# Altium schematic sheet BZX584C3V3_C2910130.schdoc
size 127 x 101 mm
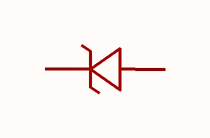
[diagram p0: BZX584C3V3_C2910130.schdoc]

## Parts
D?  bzx584c3v3_c2910130  [SOD-523_L1.2-W0.8-LS1.6-RD-2]  (value not drawn)

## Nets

Not connected (* = marked no-connect by the designer): D? 1(C) 2(A)

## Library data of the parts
D? = bzx584c3v3_c2910130: 二极管配置:1个独立式;稳压值(标称值):3.3V;稳压值(范围):3.1V~3.5V;耗散功率(Pd):150mW;; Manufacturer: CJ(江苏长电/长晶); AddInBom: yes; ModelId: a6fcdc3447de4b4888d5e65d03861b6b; ModelTransform: 62.992,31.496,0,0,0,0,0,0,0; Diode Configuration: 1个独立式; Zener Voltage(Nom): 3.3V; Reverse Leakage Current (Ir): 5uA@1V; Pd - Power Dissipation: 150mW; Impedance(Zzt): 95Ω; Impedance(Zzk): 600Ω; Operating Junction Temperature Range: -55℃~+150℃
